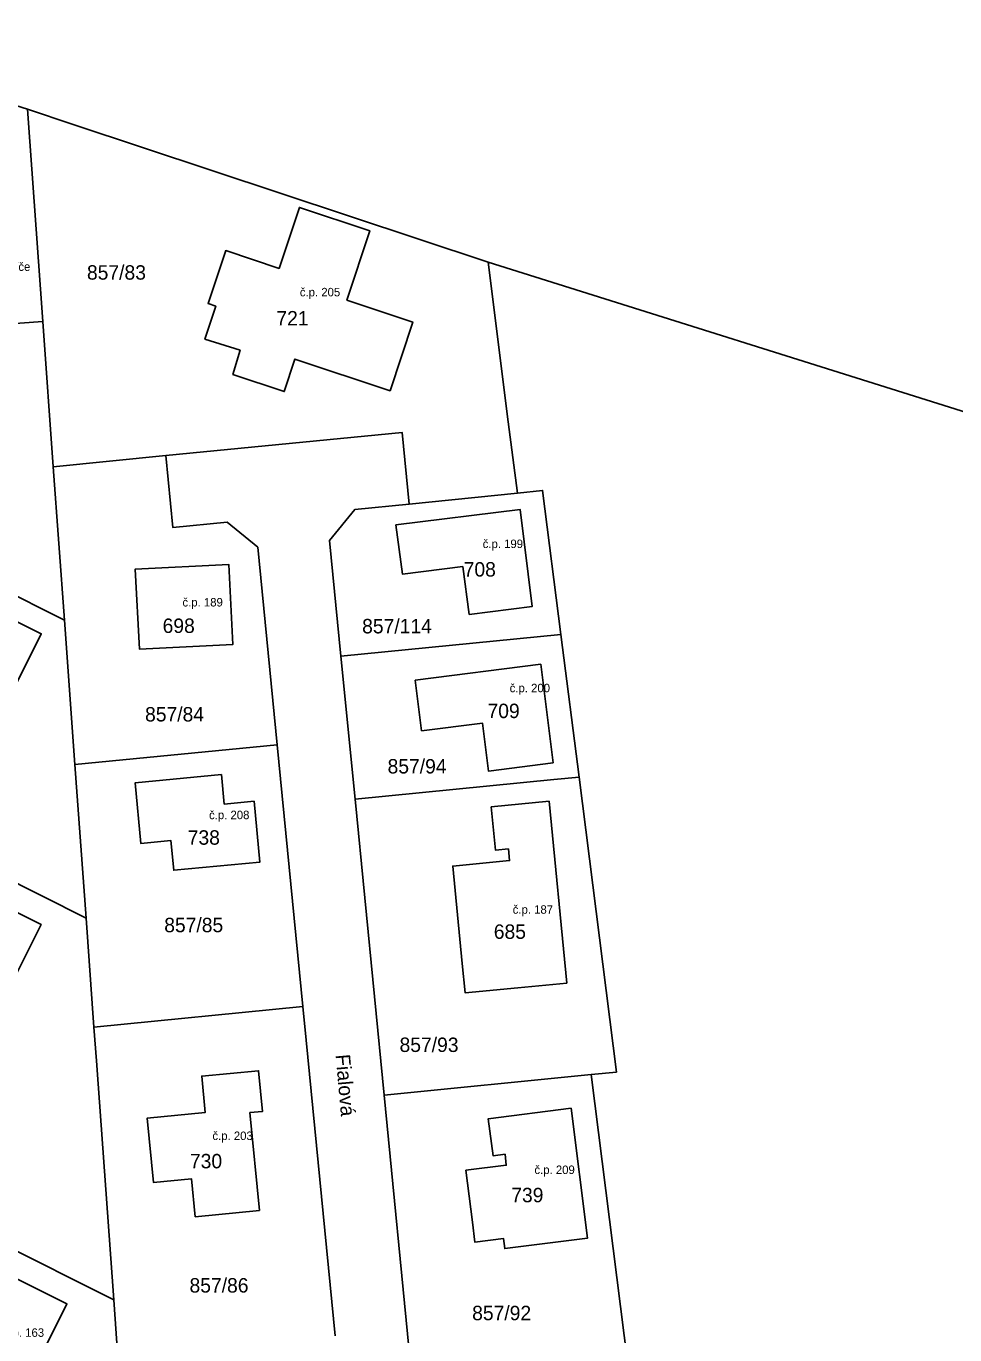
# Model space of a CAD drawing. Extents: x -887272 to -880188, y -1026687 to -1021896.
# Drawn here: x -886250.1 to -886140.7, y -1024387 to -1024232.7 of the extents above; entities that cross this region are included whole.
import ezdxf

# ---------------------------------------------------------------- set-up
doc = ezdxf.new("R2010")
doc.units = 0
for name, color, linetype in [('Definiční body', 7, 'Continuous'), ('Hranice parcel', 7, 'Continuous'), ('Parcelní čísla', 7, 'Continuous'), ('Polygon budovy', 7, 'Continuous'), ('Pop  PČ popisy', 7, 'Continuous')]:
    doc.layers.add(name, color=color, linetype=linetype)

msp = doc.modelspace()

# ---------------------------------------------------------------- linework, layer by layer
at = {"layer": 'Hranice parcel'}
for p, q in [((-886280.58, -1024232.7), (-886250, -1024242.5)), ((-886248.19, -1024267.54), (-886250, -1024242.5)), ((-886250, -1024242.5), (-886244.6, -1024244.29)), ((-886244.6, -1024244.29), (-886195.7, -1024260.53)), ((-886195.7, -1024260.53), (-886134.08, -1024279.92)), ((-886287.98, -1024270.37), (-886248.19, -1024267.54)), ((-886246.95, -1024284.65), (-886248.19, -1024267.54)), ((-886246.95, -1024284.65), (-886233.7, -1024283.34)), ((-886245.63, -1024302.75), (-886246.95, -1024284.65)), ((-886205.01, -1024289.05), (-886192.24, -1024287.75)), ((-886272.78, -1024289.17), (-886245.63, -1024302.75)), ((-886244.4, -1024319.78), (-886245.63, -1024302.75)), ((-886187.11, -1024304.43), (-886213.04, -1024306.99)), ((-886187.11, -1024304.43), (-886184.97, -1024321.26)), ((-886211.38, -1024323.85), (-886213.04, -1024306.99)), ((-886244.4, -1024319.78), (-886220.56, -1024317.43)), ((-886220.56, -1024317.43), (-886217.52, -1024348.31)), ((-886243.09, -1024337.87), (-886244.4, -1024319.78)), ((-886207.95, -1024358.74), (-886211.38, -1024323.85)), ((-886261.28, -1024328.76), (-886243.09, -1024337.87)), ((-886242.16, -1024350.73), (-886243.09, -1024337.87)), ((-886242.16, -1024350.73), (-886217.52, -1024348.31)), ((-886183.54, -1024356.31), (-886207.95, -1024358.74)), ((-886183.54, -1024356.31), (-886179.13, -1024391.05)), ((-886204.52, -1024393.61), (-886207.95, -1024358.74)), ((-886256.6, -1024374.49), (-886239.83, -1024382.88)), ((-886239.34, -1024389.68), (-886239.83, -1024382.88))]:
    msp.add_line(p, q, dxfattribs=at)
for points in [[(-886219.72, -1024275.78), (-886225.77, -1024273.77), (-886224.93, -1024270.92), (-886229.07, -1024269.6), (-886227.79, -1024265.72), (-886228.7, -1024265.42), (-886226.62, -1024259.17), (-886220.33, -1024261.26), (-886217.94, -1024254.08), (-886209.64, -1024256.82), (-886212.33, -1024264.99), (-886204.57, -1024267.59), (-886207.25, -1024275.69), (-886218.47, -1024271.96), (-886219.72, -1024275.78)], [(-886195.7, -1024260.53), (-886193.31, -1024279.36), (-886192.24, -1024287.75)], [(-886205.01, -1024289.05), (-886205.84, -1024280.6), (-886233.7, -1024283.34)], [(-886233.7, -1024283.34), (-886232.87, -1024291.81), (-886226.47, -1024291.17), (-886222.85, -1024294.14), (-886220.56, -1024317.43)], [(-886192.24, -1024287.75), (-886189.26, -1024287.45), (-886187.11, -1024304.43)], [(-886213.04, -1024306.99), (-886214.38, -1024293.33), (-886211.42, -1024289.7), (-886205.01, -1024289.05)], [(-886191.92, -1024289.69), (-886190.48, -1024301.12), (-886197.92, -1024302.06), (-886198.67, -1024296.43), (-886205.8, -1024297.3), (-886206.55, -1024291.52), (-886191.92, -1024289.69)], [(-886258.75, -1024312.22), (-886258.16, -1024311.02), (-886268.26, -1024305.98), (-886267.59, -1024304.66), (-886273.4, -1024301.75), (-886269.45, -1024293.85), (-886248.37, -1024304.35), (-886252.99, -1024313.61), (-886255.46, -1024312.36), (-886256.04, -1024313.55), (-886258.75, -1024312.22)], [(-886225.77, -1024305.6), (-886236.78, -1024306.18), (-886237.31, -1024296.74), (-886226.26, -1024296.16), (-886225.77, -1024305.6)], [(-886204.28, -1024309.8), (-886189.49, -1024307.94), (-886188.03, -1024319.56), (-886195.66, -1024320.53), (-886196.37, -1024314.88), (-886203.53, -1024315.78), (-886204.28, -1024309.8)], [(-886236.61, -1024329.09), (-886237.28, -1024321.92), (-886227.12, -1024320.95), (-886226.8, -1024324.42), (-886223.28, -1024324.1), (-886222.59, -1024331.27), (-886232.75, -1024332.23), (-886233.08, -1024328.74), (-886236.61, -1024329.09)], [(-886184.97, -1024321.26), (-886187.95, -1024321.55), (-886211.38, -1024323.85)], [(-886184.97, -1024321.26), (-886180.56, -1024356.03), (-886183.54, -1024356.31)], [(-886198.39, -1024346.69), (-886198.73, -1024343.21), (-886199.85, -1024331.75), (-886193.16, -1024331.1), (-886193.29, -1024329.71), (-886194.83, -1024329.86), (-886195.32, -1024324.76), (-886188.51, -1024324.1), (-886186.42, -1024345.53), (-886192.18, -1024346.09), (-886198.39, -1024346.69)], [(-886259.19, -1024340.23), (-886256.38, -1024334.63), (-886248.39, -1024338.62), (-886256.94, -1024355.69), (-886262.42, -1024352.95), (-886261.75, -1024351.61), (-886265.81, -1024349.57), (-886260.74, -1024339.45), (-886259.19, -1024340.23)], [(-886217.52, -1024348.31), (-886217.13, -1024352.27), (-886213.7, -1024387.12)], [(-886239.83, -1024382.88), (-886241.87, -1024354.71), (-886242.16, -1024350.73)], [(-886230.23, -1024373.09), (-886230.66, -1024368.6), (-886235.15, -1024369.05), (-886235.88, -1024361.46), (-886229.04, -1024360.79), (-886229.45, -1024356.51), (-886222.75, -1024355.87), (-886222.27, -1024360.67), (-886223.76, -1024360.81), (-886222.64, -1024372.35), (-886230.23, -1024373.09)], [(-886193.69, -1024365.72), (-886195.1, -1024365.9), (-886195.67, -1024361.54), (-886185.91, -1024360.3), (-886183.96, -1024375.6), (-886193.72, -1024376.84), (-886193.86, -1024375.66), (-886197.24, -1024376.09), (-886197.54, -1024373.71), (-886198.31, -1024367.61), (-886193.55, -1024367.02), (-886193.69, -1024365.72)], [(-886245.34, -1024383.36), (-886251.15, -1024395.02), (-886261.02, -1024390.1), (-886255.2, -1024378.44), (-886245.34, -1024383.36)]]:
    msp.add_lwpolyline(points, dxfattribs=at)
at = {"layer": 'Polygon budovy'}
for points in [[(-886229.07, -1024269.6), (-886224.93, -1024270.92), (-886225.77, -1024273.77), (-886219.72, -1024275.78), (-886218.47, -1024271.96), (-886207.25, -1024275.69), (-886204.57, -1024267.59), (-886212.33, -1024264.99), (-886209.64, -1024256.82), (-886217.94, -1024254.08), (-886220.33, -1024261.26), (-886226.62, -1024259.17), (-886228.7, -1024265.42), (-886227.79, -1024265.72)], [(-886206.55, -1024291.52), (-886205.8, -1024297.3), (-886198.67, -1024296.43), (-886197.92, -1024302.06), (-886190.48, -1024301.12), (-886191.92, -1024289.69)], [(-886269.45, -1024293.85), (-886273.4, -1024301.75), (-886267.59, -1024304.66), (-886268.26, -1024305.98), (-886258.16, -1024311.02), (-886258.75, -1024312.22), (-886256.04, -1024313.55), (-886255.46, -1024312.36), (-886252.99, -1024313.61), (-886248.37, -1024304.35)], [(-886237.31, -1024296.74), (-886236.78, -1024306.18), (-886225.77, -1024305.6), (-886226.26, -1024296.16)], [(-886204.28, -1024309.8), (-886203.53, -1024315.78), (-886196.37, -1024314.88), (-886195.66, -1024320.53), (-886188.03, -1024319.56), (-886189.49, -1024307.94)], [(-886232.75, -1024332.23), (-886222.59, -1024331.27), (-886223.28, -1024324.1), (-886226.8, -1024324.42), (-886227.12, -1024320.95), (-886237.28, -1024321.92), (-886236.61, -1024329.09), (-886233.08, -1024328.74)], [(-886195.32, -1024324.76), (-886194.83, -1024329.86), (-886193.29, -1024329.71), (-886193.16, -1024331.1), (-886199.85, -1024331.75), (-886198.73, -1024343.21), (-886198.39, -1024346.69), (-886192.18, -1024346.09), (-886186.42, -1024345.53), (-886188.51, -1024324.1)], [(-886261.75, -1024351.61), (-886262.42, -1024352.95), (-886256.94, -1024355.69), (-886248.39, -1024338.62), (-886256.38, -1024334.63), (-886259.19, -1024340.23), (-886260.74, -1024339.45), (-886265.81, -1024349.57)], [(-886230.23, -1024373.09), (-886222.64, -1024372.35), (-886223.76, -1024360.81), (-886222.27, -1024360.67), (-886222.75, -1024355.87), (-886229.45, -1024356.51), (-886229.04, -1024360.79), (-886235.88, -1024361.46), (-886235.15, -1024369.05), (-886230.66, -1024368.6)], [(-886193.86, -1024375.66), (-886193.72, -1024376.84), (-886183.96, -1024375.6), (-886185.91, -1024360.3), (-886195.67, -1024361.54), (-886195.1, -1024365.9), (-886193.69, -1024365.72), (-886193.55, -1024367.02), (-886198.31, -1024367.61), (-886197.54, -1024373.71), (-886197.24, -1024376.09)], [(-886255.2, -1024378.44), (-886261.02, -1024390.1), (-886251.15, -1024395.02), (-886245.34, -1024383.36)]]:
    msp.add_lwpolyline(points, close=True, dxfattribs=at)

# ---------------------------------------------------------------- texts
at = {"layer": 'Definiční body'}
for s, p in [('bez čp/če', (-886255.38, -1024261.56)), ('č.p. 205', (-886217.88, -1024264.56)), ('č.p. 199', (-886196.33, -1024294.24)), ('č.p. 189', (-886231.72, -1024301.13)), ('č.p. 200', (-886193.15, -1024311.24)), ('č.p. 208', (-886228.59, -1024326.21)), ('č.p. 187', (-886192.79, -1024337.36)), ('č.p. 203', (-886228.19, -1024364.04)), ('č.p. 209', (-886190.23, -1024368.05)), ('č.p. 163', (-886252.79, -1024387.25))]:
    msp.add_text(s, height=1, dxfattribs=at).set_placement(p)
at = {"layer": 'Parcelní čísla'}
for s, p in [('857/83', (-886242.98, -1024262.59)), ('721', (-886220.65, -1024267.99)), ('708', (-886198.57, -1024297.6)), ('698', (-886234.06, -1024304.25)), ('857/114', (-886210.54, -1024304.3)), ('857/84', (-886236.13, -1024314.69)), ('709', (-886195.76, -1024314.29)), ('857/94', (-886207.54, -1024320.82)), ('738', (-886231.1, -1024329.22)), ('857/85', (-886233.87, -1024339.54)), ('685', (-886195.02, -1024340.32)), ('857/93', (-886206.13, -1024353.66)), ('730', (-886230.84, -1024367.38)), ('739', (-886192.96, -1024371.38)), ('857/86', (-886230.89, -1024382.03)), ('857/92', (-886197.57, -1024385.29))]:
    msp.add_text(s, height=1.7, dxfattribs=at).set_placement(p)
at = {"layer": 'Pop  PČ popisy'}
msp.add_text('Fialová', height=1.7, rotation=275, dxfattribs=at).set_placement((-886213.67, -1024354))

doc.saveas('drawing.dxf')
